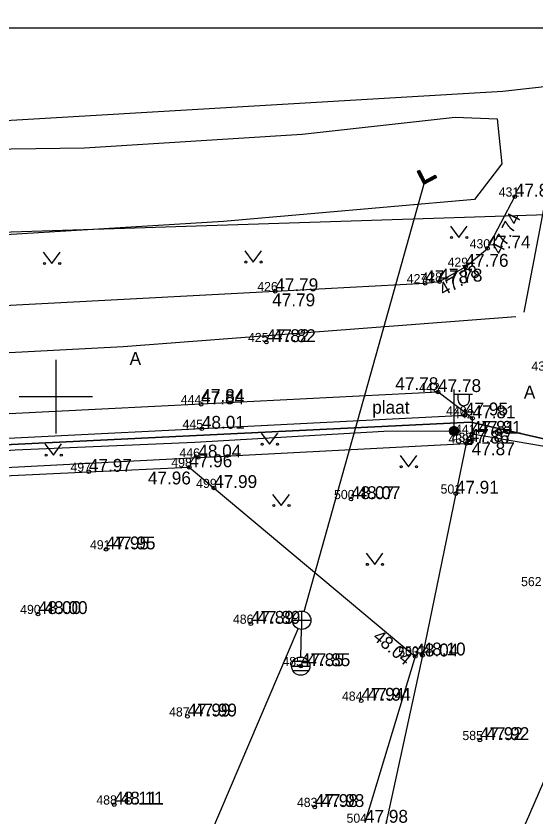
# Model space of a CAD drawing. Extents: x 640876 to 641418, y 6455595 to 6456085.
# Drawn here: x 641197.83 to 641226.13, y 6455977.11 to 6456020.73 of the extents above; entities that cross this region are included whole.
import ezdxf

# ---------------------------------------------------------------- set-up
doc = ezdxf.new("R2010")
doc.units = 0
for name, color, linetype in [('AED', 7, 'Continuous'), ('HALJASTUS', 7, 'Continuous'), ('KORGUS', 7, 'Continuous'), ('MOOTKORG', 7, 'Continuous'), ('MOOTMPUNKT', 7, 'Continuous'), ('MOOTNR', 7, 'Continuous'), ('MOOTPIIR', 7, 'Continuous'), ('MPKAABEL', 7, 'Continuous'), ('PIIR', 7, 'Continuous'), ('POST', 7, 'Continuous'), ('SKKAEV', 7, 'Continuous'), ('SKTRASS', 7, 'Continuous'), ('TEE', 7, 'Continuous'), ('VEEKOGU', 7, 'Continuous'), ('VORK', 7, 'Continuous'), ('VORMISTUS', 7, 'Continuous'), ('VTRASS', 7, 'Continuous')]:
    doc.layers.add(name, color=color, linetype=linetype)

msp = doc.modelspace()

# ---------------------------------------------------------------- linework, layer by layer
at = {"layer": 'AED'}
for p, q in [((641222.397, 6455997.662), (641222.397, 6455997.412)), ((641222.397, 6455997.662), (641222.647, 6455997.662)), ((641222.647, 6455997.662), (641222.647, 6455997.412)), ((641222.397, 6455997.412), (641222.647, 6455997.412))]:
    msp.add_line(p, q, dxfattribs=at)
msp.add_lwpolyline([(641160.606, 6455994.253), (641178.047, 6455995.168), (641191.652, 6455995.856), (641207.752, 6455996.687), (641222.341, 6455997.449), (641221.765, 6455994.718), (641219.959, 6455985.906), (641217.708, 6455975.561), (641214.2, 6455967.017), (641207.311, 6455950.541), (641202.719, 6455939.647), (641198.916, 6455930.446)], dxfattribs=at)
at = {"layer": 'HALJASTUS'}
for p, q in [((641221.477, 6456009.28), (641221.94, 6456008.673)), ((641221.94, 6456008.673), (641222.386, 6456009.28)), ((641199.318, 6456007.86), (641199.781, 6456007.253)), ((641199.781, 6456007.253), (641200.227, 6456007.86)), ((641210.279, 6456007.938), (641210.742, 6456007.332)), ((641210.742, 6456007.332), (641211.188, 6456007.938)), ((641211.168, 6455998.01), (641211.632, 6455997.404)), ((641211.632, 6455997.404), (641212.077, 6455998.01)), ((641199.407, 6455997.424), (641199.871, 6455996.818)), ((641199.871, 6455996.818), (641200.316, 6455997.424)), ((641218.739, 6455996.793), (641219.202, 6455996.186)), ((641219.202, 6455996.186), (641219.648, 6455996.793)), ((641211.799, 6455994.674), (641212.263, 6455994.067)), ((641212.263, 6455994.067), (641212.708, 6455994.674)), ((641216.891, 6455991.473), (641217.355, 6455990.866)), ((641217.355, 6455990.866), (641217.8, 6455991.473))]:
    msp.add_line(p, q, dxfattribs=at)
for centre in [(641221.539, 6456008.673), (641222.368, 6456008.673), (641199.38, 6456007.253), (641200.209, 6456007.253), (641210.341, 6456007.332), (641211.17, 6456007.332), (641211.231, 6455997.404), (641212.06, 6455997.404), (641199.47, 6455996.818), (641200.298, 6455996.818), (641218.801, 6455996.186), (641219.63, 6455996.186), (641211.862, 6455994.067), (641212.69, 6455994.067), (641216.954, 6455990.866), (641217.782, 6455990.866)]:
    msp.add_circle(centre, 0.055, dxfattribs=at)
at = {"layer": 'KORGUS'}
for centre in [(641223.496, 6456008.075), (641220.874, 6456006.265), (641211.938, 6456005.745), (641211.457, 6456002.971), (641220.802, 6456000.252), (641207.904, 6455999.587), (641222.651, 6455997.98), (641222.522, 6455997.537), (641207.259, 6455996.159), (641216.066, 6455994.421), (641202.732, 6455991.683), (641199.033, 6455988.161), (641210.614, 6455987.63), (641219.562, 6455985.852), (641213.332, 6455985.323), (641216.622, 6455983.439), (641207.163, 6455982.581), (641223.077, 6455981.297), (641203.18, 6455977.785), (641214.095, 6455977.652)]:
    msp.add_circle(centre, 0.1, dxfattribs=at)
at = {"layer": 'MOOTMPUNKT'}
for centre in [(641224.979, 6456010.896), (641223.496, 6456008.075), (641222.296, 6456007.072), (641220.1, 6456006.174), (641220.874, 6456006.265), (641211.938, 6456005.745), (641211.457, 6456002.971), (641220.802, 6456000.252), (641207.904, 6455999.587), (641222.264, 6455998.978), (641222.677, 6455998.823), (641207.946, 6455998.252), (641222.651, 6455997.98), (641222.341, 6455997.449), (641222.522, 6455997.537), (641207.752, 6455996.687), (641207.259, 6455996.159), (641201.796, 6455995.908), (641208.614, 6455995.025), (641216.066, 6455994.421), (641221.765, 6455994.718), (641202.732, 6455991.683), (641199.033, 6455988.161), (641210.614, 6455987.63), (641219.562, 6455985.852), (641219.959, 6455985.906), (641213.332, 6455985.323), (641216.622, 6455983.439), (641207.163, 6455982.581), (641223.077, 6455981.297), (641203.18, 6455977.785), (641214.095, 6455977.652)]:
    msp.add_circle(centre, 0.1, dxfattribs=at)
at = {"layer": 'MOOTPIIR'}
msp.add_lwpolyline([(641060.916, 6455895.936), (641100.061, 6455950.482), (641099.586, 6455952.159), (641069.132, 6455984.035), (641066.132, 6455988.623), (641076.463, 6456005.049), (641230.642, 6456010.048), (641237.36, 6455995.24), (641237.24, 6455992.81), (641236.258, 6455990.888), (641229.041, 6455971.315), (641203.026, 6455909.57), (641225.257, 6455906.847), (641239.512, 6455898.491), (641200.195, 6455851.697), (641192.016, 6455859.099), (641169.785, 6455829.138), (641192.025, 6455807.568), (641252.96, 6455758.075), (641231.388, 6455736.74), (641191.474, 6455775.975), (641152.419, 6455787.914), (641136.351, 6455788.307), (641049.066, 6455856.043)], dxfattribs=at)
at = {"layer": 'MPKAABEL'}
msp.add_lwpolyline([(641152.745, 6455994.399), (641157.936, 6455994.715), (641172.717, 6455995.627), (641184.197, 6455996.113), (641197.79, 6455997.111), (641207.568, 6455997.528), (641217.849, 6455998.12), (641221.671, 6455998.134)], dxfattribs=at)
at = {"layer": 'PIIR'}
for points in [[(640981.25, 6456014.49), (641018.11, 6456020.73), (641048.89, 6456017.91), (641071.8, 6456014.51), (641086.43, 6456012.78), (641194.48, 6456014.88), (641224.33, 6456016.64), (641234.96, 6456017.83), (641241.97, 6456004.88), (641237.36, 6455995.24), (641222.58, 6455998.61), (641084.84, 6455991.92), (641061.51, 6455993.34), (640998.61, 6455989.99), (640969.54, 6455988.44)], [(641222.58, 6455998.61), (641237.36, 6455995.24), (641235.34, 6455991.29), (641228.11, 6455971.68), (641220.5, 6455953.19), (641213.41, 6455936.25), (641201.58, 6455908.74), (641224.93, 6455905.88), (641191.87, 6455860.58), (641157.02, 6455885.66), (641160.91, 6455891.99), (641102.26, 6455951.82), (641074.95, 6455979.64), (641084.84, 6455991.92)]]:
    msp.add_lwpolyline(points, close=True, dxfattribs=at)
at = {"layer": 'POST'}
for p, q in [((641221.671, 6455998.384), (641221.671, 6456000.384)), ((641221.671, 6456000.134), (641222.671, 6456000.134)), ((641221.898, 6455999.813), (641221.898, 6456000.134)), ((641222.51, 6455999.813), (641222.51, 6456000.134)), ((641221.671, 6455998.134), (641221.671, 6455998.134))]:
    msp.add_line(p, q, dxfattribs=at)
for radius in [0.25, 0.225, 0.2, 0.175, 0.15, 0.125, 0.1, 0.075, 0.05, 0.025]:
    msp.add_circle((641221.671, 6455998.134), radius, dxfattribs=at)
msp.add_arc((641222.204, 6455999.813), 0.306, 180, 0, dxfattribs=at)
at = {"layer": 'SKKAEV'}
for p, q in [((641213.381, 6455987.322), (641213.381, 6455988.322)), ((641212.881, 6455987.822), (641213.881, 6455987.822)), ((641212.832, 6455985.323), (641213.832, 6455985.323)), ((641213.762, 6455985.573), (641212.902, 6455985.573)), ((641213.762, 6455985.073), (641212.902, 6455985.073))]:
    msp.add_line(p, q, dxfattribs=at)
for centre in [(641213.381, 6455987.822), (641213.332, 6455985.323)]:
    msp.add_circle(centre, 0.5, dxfattribs=at)
at = {"layer": 'SKTRASS'}
for p, q in [((641219.791, 6456012.324), (641219.665, 6456012.258)), ((641219.79, 6456012.323), (641219.796, 6456012.009)), ((641219.791, 6456012.324), (641220.088, 6456011.761)), ((641219.665, 6456012.258), (641220.028, 6456011.569)), ((641219.691, 6456012.271), (641219.692, 6456012.206)), ((641219.716, 6456012.284), (641219.718, 6456012.157)), ((641219.728, 6456012.291), (641220.058, 6456011.665)), ((641219.741, 6456012.297), (641219.744, 6456012.108)), ((641219.766, 6456012.31), (641219.77, 6456012.058)), ((641219.816, 6456012.276), (641219.822, 6456011.96)), ((641219.842, 6456012.227), (641219.848, 6456011.911)), ((641219.868, 6456012.178), (641219.874, 6456011.862)), ((641219.894, 6456012.129), (641219.9, 6456011.813)), ((641219.92, 6456012.08), (641219.925, 6456011.764)), ((641219.946, 6456012.031), (641219.951, 6456011.714)), ((641219.972, 6456011.982), (641219.977, 6456011.665)), ((641219.997, 6456011.932), (641220.003, 6456011.616)), ((641220.023, 6456011.883), (641220.029, 6456011.569)), ((641220.028, 6456011.569), (641220.717, 6456011.932)), ((641220.058, 6456011.665), (641220.683, 6456011.995)), ((641220.088, 6456011.761), (641220.65, 6456012.058)), ((641220.323, 6456011.885), (641220.326, 6456011.726)), ((641220.348, 6456011.898), (641220.351, 6456011.739)), ((641220.373, 6456011.911), (641220.376, 6456011.752)), ((641220.398, 6456011.925), (641220.4, 6456011.765)), ((641220.422, 6456011.938), (641220.425, 6456011.778)), ((641220.447, 6456011.951), (641220.45, 6456011.791)), ((641220.472, 6456011.964), (641220.475, 6456011.804)), ((641220.497, 6456011.977), (641220.5, 6456011.817)), ((641220.521, 6456011.99), (641220.524, 6456011.83)), ((641220.546, 6456012.003), (641220.549, 6456011.843)), ((641220.571, 6456012.016), (641220.574, 6456011.856)), ((641220.596, 6456012.029), (641220.599, 6456011.869)), ((641220.621, 6456012.042), (641220.623, 6456011.883)), ((641220.645, 6456012.055), (641220.648, 6456011.896)), ((641220.65, 6456012.058), (641220.717, 6456011.932)), ((641220.671, 6456012.018), (641220.673, 6456011.909)), ((641220.697, 6456011.969), (641220.698, 6456011.922)), ((641220.049, 6456011.834), (641220.054, 6456011.582)), ((641220.075, 6456011.785), (641220.078, 6456011.596)), ((641220.1, 6456011.768), (641220.103, 6456011.609)), ((641220.125, 6456011.781), (641220.128, 6456011.622)), ((641220.15, 6456011.794), (641220.153, 6456011.635)), ((641220.175, 6456011.807), (641220.178, 6456011.648)), ((641220.199, 6456011.82), (641220.202, 6456011.661)), ((641220.224, 6456011.833), (641220.227, 6456011.674)), ((641220.249, 6456011.846), (641220.252, 6456011.687)), ((641220.274, 6456011.859), (641220.277, 6456011.7)), ((641220.299, 6456011.872), (641220.301, 6456011.713))]:
    msp.add_line(p, q, dxfattribs=at)
for points in [[(641213.516, 6455988.303), (641220.058, 6456011.665)], [(641204.199, 6455966.239), (641213.185, 6455987.362)], [(641213.342, 6455985.823), (641213.371, 6455987.322)]]:
    msp.add_lwpolyline(points, dxfattribs=at)
at = {"layer": 'TEE'}
for points in [[(641191.337, 6456004.985), (641191.674, 6456004.679), (641211.938, 6456005.745), (641220.1, 6456006.174), (641220.874, 6456006.265), (641222.296, 6456007.072), (641223.496, 6456008.075), (641224.979, 6456010.896)], [(641222.651, 6455997.98), (641228.089, 6455997.045), (641228.877, 6456000.338), (641227.203, 6456000.773), (641226.862, 6456001.079), (641226.863, 6456001.414), (641228.525, 6456010.185)], [(641222.651, 6455997.98), (641222.677, 6455998.823), (641220.802, 6456000.252), (641207.904, 6455999.587), (641192.028, 6455998.799), (641178.983, 6455998.116), (641163.081, 6455997.316), (641161.565, 6455996.932), (641160.895, 6455996.447), (641160.425, 6455995.795), (641160.271, 6455995.032), (641160.279, 6455994.218), (641160.404, 6455993.367), (641161.226, 6455991.415), (641162.227, 6455990.048), (641167.668, 6455994.304), (641183.068, 6455995.004), (641194.491, 6455995.56), (641201.796, 6455995.908), (641207.259, 6455996.159), (641208.614, 6455995.025), (641219.562, 6455985.852), (641216.822, 6455976.794)], [(641222.264, 6455998.978), (641207.946, 6455998.252), (641191.921, 6455997.451), (641178.778, 6455996.781), (641160.679, 6455995.901)]]:
    msp.add_lwpolyline(points, dxfattribs=at)
at = {"layer": 'VEEKOGU'}
for points in [[(641194.894, 6456013.457), (641201.564, 6456013.556), (641213.403, 6456014.295), (641221.739, 6456015.214), (641224.027, 6456015.139), (641224.282, 6456012.679), (641222.786, 6456010.743), (641209.122, 6456009.547), (641192.523, 6456008.523)], [(641223.639, 6455963.147), (641230.651, 6455980.138), (641229.496, 6455980.913), (641227.432, 6455981.074), (641220.221, 6455964.447), (641220.969, 6455963.511), (641222.903, 6455962.539), (641223.639, 6455963.147)]]:
    msp.add_lwpolyline(points, dxfattribs=at)
at = {"layer": 'VORK'}
for p, q in [((641200, 6456002), (641200, 6455998)), ((641198, 6456000), (641202, 6456000))]:
    msp.add_line(p, q, dxfattribs=at)
at = {"layer": 'VORMISTUS'}
msp.add_line((641035.115, 6456020.09), (641256.302, 6456020.09), dxfattribs=at)
at = {"layer": 'VTRASS'}
for points in [[(641225.493, 6456004.596), (641227.34, 6456014.292)], [(641064.363, 6455995.75), (641076.979, 6455996.021), (641104.204, 6455997.462), (641127.864, 6455998.715), (641152.811, 6456000.037), (641188.143, 6456001.908), (641203.655, 6456002.73), (641225.036, 6456004.365)]]:
    msp.add_lwpolyline(points, dxfattribs=at)

# ---------------------------------------------------------------- texts
at = {"layer": 'KORGUS'}
for s, rotation, p in [('47.74', 62.7388, (641224.247, 6456007.691)), ('47.78', 29.4891, (641221.101, 6456005.469)), ('48.04', 320.0602, (641217.205, 6455986.827))]:
    msp.add_text(s, height=0.7, rotation=rotation, dxfattribs=at).set_placement(p)
for s, p in [('47.79', (641211.773, 6456004.92)), ('47.82', (641211.807, 6456002.971)), ('47.78', (641218.474, 6456000.355)), ('47.84', (641207.919, 6455999.713)), ('47.81', (641223.001, 6455997.98)), ('47.87', (641222.636, 6455996.81)), ('47.96', (641205.008, 6455995.221)), ('48.07', (641216.416, 6455994.421)), ('47.95', (641203.082, 6455991.683)), ('48.00', (641199.383, 6455988.161)), ('47.89', (641210.964, 6455987.63)), ('47.85', (641213.682, 6455985.323)), ('47.94', (641216.972, 6455983.439)), ('47.99', (641207.513, 6455982.581)), ('47.92', (641223.427, 6455981.297)), ('48.11', (641203.53, 6455977.785)), ('47.98', (641214.445, 6455977.652))]:
    msp.add_text(s, height=0.7, dxfattribs=at).set_placement(p)
at = {"layer": 'MOOTKORG'}
for s, p in [('47.80', (641224.979, 6456010.896)), ('47.74', (641223.496, 6456008.075)), ('47.76', (641222.296, 6456007.072)), ('47.78', (641220.1, 6456006.174)), ('47.78', (641220.874, 6456006.265)), ('47.79', (641211.938, 6456005.745)), ('47.82', (641211.457, 6456002.971)), ('47.78', (641220.802, 6456000.252)), ('47.84', (641207.904, 6455999.587)), ('47.95', (641222.264, 6455998.978)), ('47.81', (641222.677, 6455998.823)), ('48.01', (641207.946, 6455998.252)), ('47.81', (641222.651, 6455997.98)), ('47.86', (641222.341, 6455997.449)), ('47.87', (641222.522, 6455997.537)), ('48.04', (641207.752, 6455996.687)), ('47.97', (641201.796, 6455995.908)), ('47.96', (641207.259, 6455996.159)), ('47.99', (641208.614, 6455995.025)), ('47.91', (641221.765, 6455994.718)), ('48.07', (641216.066, 6455994.421)), ('47.95', (641202.732, 6455991.683)), ('48.00', (641199.033, 6455988.161)), ('47.89', (641210.614, 6455987.63)), ('48.10', (641219.959, 6455985.906)), ('48.04', (641219.562, 6455985.852)), ('47.85', (641213.332, 6455985.323)), ('47.94', (641216.622, 6455983.439)), ('47.99', (641207.163, 6455982.581)), ('47.92', (641223.077, 6455981.297)), ('48.11', (641203.18, 6455977.785)), ('47.98', (641214.095, 6455977.652)), ('47.98', (641216.822, 6455976.794))]:
    msp.add_text(s, height=0.7, dxfattribs=at).set_placement(p)
at = {"layer": 'MOOTNR'}
for s, p in [('431', (641224.104, 6456010.896)), ('430', (641222.521, 6456008.075)), ('429', (641221.321, 6456007.072)), ('427', (641219.1, 6456006.174)), ('428', (641219.899, 6456006.265)), ('426', (641210.963, 6456005.745)), ('425', (641210.457, 6456002.971)), ('433', (641225.888, 6456001.414)), ('443', (641219.777, 6456000.252)), ('444', (641206.804, 6455999.587)), ('440', (641221.239, 6455998.978)), ('442', (641221.627, 6455998.823)), ('445', (641206.896, 6455998.252)), ('441', (641221.726, 6455997.98)), ('439', (641221.366, 6455997.449)), ('438', (641221.547, 6455997.537)), ('446', (641206.727, 6455996.687)), ('498', (641206.284, 6455996.159)), ('497', (641200.796, 6455995.908)), ('499', (641207.639, 6455995.025)), ('500', (641215.141, 6455994.421)), ('501', (641220.94, 6455994.718)), ('491', (641201.857, 6455991.683)), ('562', (641225.32, 6455989.679)), ('490', (641198.058, 6455988.161)), ('486', (641209.639, 6455987.63)), ('503', (641218.637, 6455985.852)), ('502', (641219.009, 6455985.906)), ('485', (641212.332, 6455985.323)), ('484', (641215.572, 6455983.439)), ('487', (641206.163, 6455982.581)), ('585', (641222.127, 6455981.297)), ('488', (641202.205, 6455977.785)), ('483', (641213.121, 6455977.652)), ('504', (641215.822, 6455976.794))]:
    msp.add_text(s, height=0.5, dxfattribs=at).set_placement(p)
at = {"layer": 'TEE'}
for s, p in [('A', (641204.016, 6456001.732)), ('A', (641225.472, 6455999.897)), ('plaat', (641217.219, 6455999.072))]:
    msp.add_text(s, height=0.7, dxfattribs=at).set_placement(p)

doc.saveas('drawing.dxf')
